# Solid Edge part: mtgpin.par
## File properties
Title: Mounting Pin
Subject: Carrier Assembly
Author: kiyo
Keywords: Mounting Pin
Comments: Mounting Pin
Template: metric.par
Last saved by: edge
Revision: 32
Application: Solid Edge
File Size: 0
Number of Sheets: 0
Number of Objects: 0
Username: kiyo
文書内容のタイプ: 0
Material: Copper
Face Style: Copper
Fill Style: ANSI33(Brass)
Virtual Style: Copper
Coef. of Thermal Exp: 1.8e-05
Thermal Conductivity: 391.0
Specific Heat: 385.0
Modulus of Elasticity: 117210869000.0
Poisson's Ratio: 0.31
Yield Stress: 275790280.0
Ultimate Stress: 310264065.0
Elongation: 0.0
Category: Macined Cylindrical
Manager: Brian Little
Company: Wheels R Us
Density: 8906
Accuracy: 0.99
Document Number: MP-101
Revision: 1
Project Name: Trolley Wheel Assembly
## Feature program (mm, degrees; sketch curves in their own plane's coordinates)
sketch for "unnamed RevolvedProtrusion 1" plane through (0, 0, 0) normal (0, -1, 0) x-axis (1, 0, 0)
  line (-56.4485, 0) -> (-56.4485, 10.25)
  line (-56.4485, 10.25) -> (-6.4485, 10.25)
  line (-6.4485, 10.25) -> (-6.4485, 18)
  line (-6.4485, 18) -> (5.5515, 18)
  line (5.5515, 18) -> (5.5515, 0)
  line (5.5515, 0) -> (-56.4485, 0)
revolve "unnamed RevolvedProtrusion 1" add finite 360 deg about sketch line (21.325, 0) -> (44.5316, 0)
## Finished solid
Body 1: solid body, 5 faces, 4 edges, 0 vertices.
  Faces by surface: plane 3, cylinder 2
  Edges by curve: circle 4
Bounding box of the edges (mm): 62.000 x 36.000 x 36.000, from (-56.4485, -18, -18) to (5.5515, 18, 18).
Cylindrical faces by radius (mm): R10.25 x1, R18 x1
Planar faces by outward normal: +x 1, -x 2
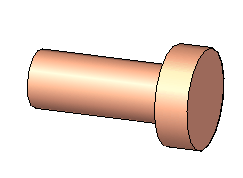
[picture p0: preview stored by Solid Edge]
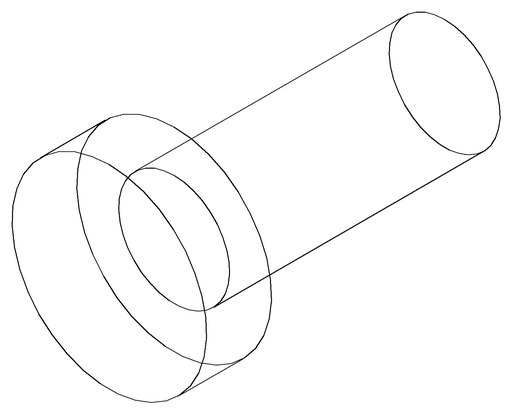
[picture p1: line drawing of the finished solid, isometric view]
